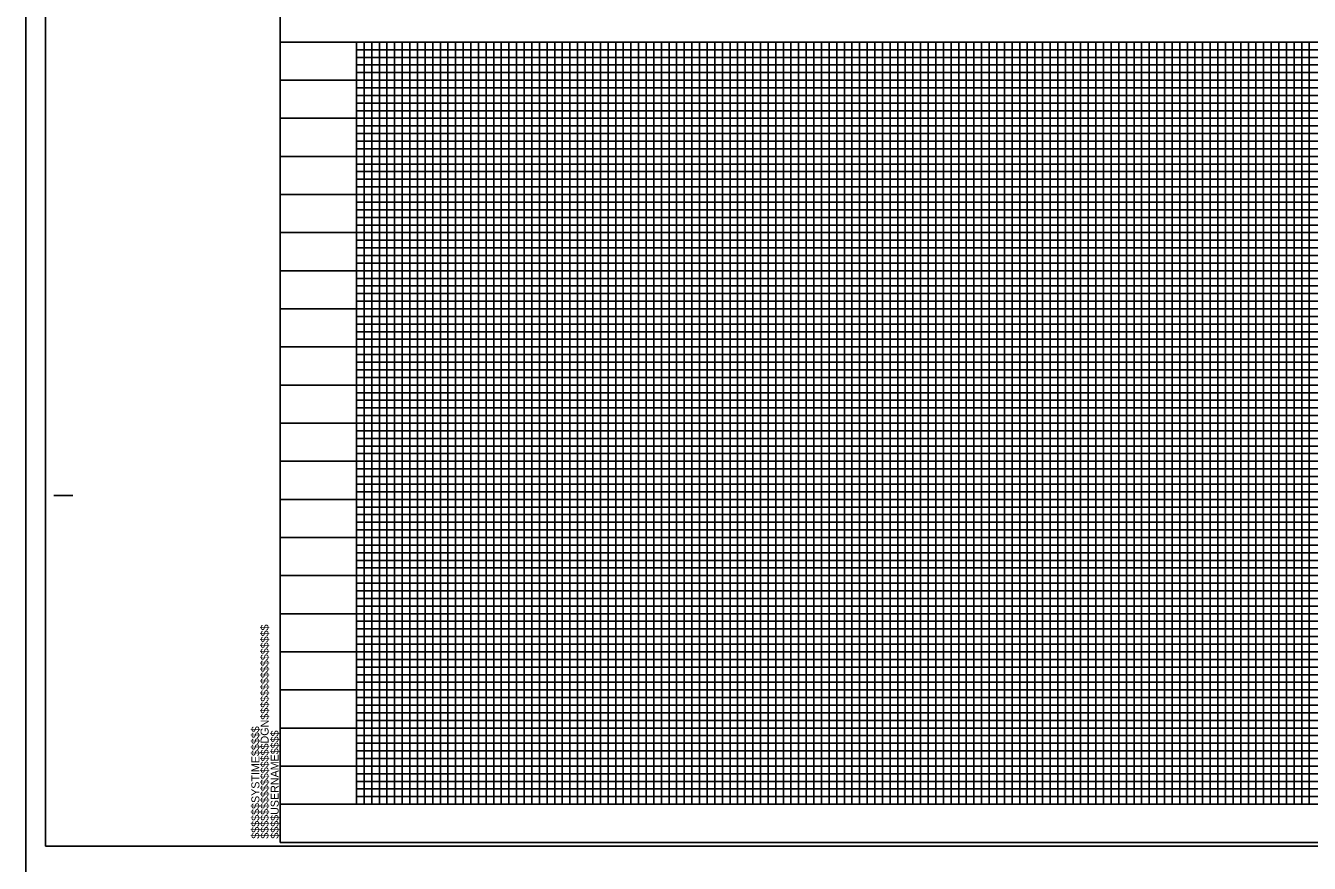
# Model space of a CAD drawing. Extents: x 1755181 to 1757273, y 729911 to 735411.
# Drawn here: x 1755181 to 1756023, y 732122 to 732672 of the extents above; entities that cross this region are included whole.
import ezdxf

# ---------------------------------------------------------------- set-up
doc = ezdxf.new("R2010")
doc.units = 0
for name, color, linetype in [('Scratch_Level_3', 7, 'Continuous'), ('Sheet Cutting Line CELL', 7, 'Continuous'), ('Sheet DOT Grid CELL', 7, 'Continuous'), ('Sheet Plot Border Inside CELL', 7, 'Continuous'), ('Sheet Plot Border Outside CELL', 7, 'Continuous'), ('Sheet Profile CELL', 7, 'Continuous'), ('Sheet Profile Grid Major CELL', 7, 'Continuous'), ('Sheet Profile Grid Middle CELL', 7, 'Continuous'), ('Sheet Profile Grid Minor CELL', 7, 'Continuous')]:
    doc.layers.add(name, color=color, linetype=linetype)

msp = doc.modelspace()

# ---------------------------------------------------------------- linework, layer by layer
at = {"layer": 'Scratch_Level_3'}
for points in [[(1755347.67, 732660.78), (1755347.67, 733185.78), (1756647.65, 733185.78), (1756647.63, 732952.8), (1756847.67, 732952.8), (1756847.67, 732660.78)], [(1755347.67, 732135.78), (1755347.67, 732660.78), (1756847.67, 732660.78), (1756847.67, 732135.78)]]:
    msp.add_lwpolyline(points, close=True, dxfattribs=at)
at = {"layer": 'Sheet Cutting Line CELL'}
msp.add_line((1755180.67, 733210.78), (1755180.67, 732110.78), dxfattribs=at)
at = {"layer": 'Sheet DOT Grid CELL'}
for p, q in [((1755347.67, 732660.78), (1756847.56, 732660.78)), ((1755397.67, 732660.78), (1755397.67, 732160.78)), ((1755447.67, 732660.78), (1755447.67, 732160.78)), ((1755497.67, 732660.78), (1755497.67, 732160.78)), ((1755547.67, 732660.78), (1755547.67, 732160.78)), ((1755597.67, 732660.78), (1755597.67, 732160.78)), ((1755647.67, 732660.78), (1755647.67, 732160.78)), ((1755697.67, 732660.78), (1755697.67, 732160.78)), ((1755747.67, 732660.78), (1755747.67, 732160.78)), ((1755797.67, 732660.78), (1755797.67, 732160.78)), ((1755847.67, 732660.78), (1755847.67, 732160.78)), ((1755897.67, 732660.78), (1755897.67, 732160.78)), ((1755947.67, 732660.78), (1755947.67, 732160.78)), ((1755997.67, 732660.78), (1755997.67, 732160.78)), ((1755347.67, 732610.78), (1756847.56, 732610.78)), ((1755347.67, 732560.78), (1756847.56, 732560.78)), ((1755347.67, 732510.78), (1756847.56, 732510.78)), ((1755347.67, 732460.78), (1756847.56, 732460.78)), ((1755347.67, 732410.78), (1756847.56, 732410.78)), ((1755347.67, 732360.78), (1756847.56, 732360.78)), ((1755347.67, 732310.78), (1756847.56, 732310.78)), ((1755347.67, 732260.78), (1756847.56, 732260.78)), ((1755347.67, 732210.78), (1756847.56, 732210.78))]:
    msp.add_line(p, q, dxfattribs=at)
at = {"layer": 'Sheet Plot Border Inside CELL'}
msp.add_lwpolyline([(1755193.67, 732133.23), (1756860.17, 732133.23), (1756860.17, 733188.33), (1755193.67, 733188.33)], close=True, dxfattribs=at)
at = {"layer": 'Sheet Plot Border Outside CELL'}
msp.add_lwpolyline([(1755180.67, 732110.78), (1756864.67, 732110.78), (1756864.67, 733210.78), (1755180.67, 733210.78)], close=True, dxfattribs=at)
at = {"layer": 'Sheet Profile CELL'}
for p, q in [((1755347.67, 732660.78), (1756847.67, 732660.78)), ((1755199.17, 732363.28), (1755211.67, 732363.28)), ((1756847.67, 732160.78), (1755347.67, 732160.78)), ((1755347.67, 732135.78), (1756847.67, 732135.78)), ((1755347.67, 732135.78), (1755347.67, 732135.78))]:
    msp.add_line(p, q, dxfattribs=at)
msp.add_lwpolyline([(1756847.67, 733185.78), (1755347.67, 733185.78), (1755347.67, 732135.78), (1756847.67, 732135.78)], close=True, dxfattribs=at)
msp.add_lwpolyline([(1755385.17, 732135.78), (1755385.17, 732135.78)], dxfattribs=at)
at = {"layer": 'Sheet Profile Grid Major CELL'}
for p, q in [((1755847.67, 732660.78), (1755897.67, 732660.78)), ((1755947.67, 732660.78), (1755997.67, 732660.78)), ((1755347.67, 732160.78), (1755347.67, 732160.78))]:
    msp.add_line(p, q, dxfattribs=at)
for points in [[(1755397.67, 732660.78), (1755397.67, 732160.78), (1755447.67, 732160.78), (1755447.67, 732660.78), (1755497.67, 732660.78), (1755497.67, 732160.78), (1755547.67, 732160.78), (1755547.67, 732660.78), (1755597.67, 732660.78), (1755597.67, 732160.78), (1755647.67, 732160.78), (1755647.67, 732660.78), (1755697.67, 732660.78), (1755697.67, 732160.78), (1755747.67, 732160.78), (1755747.67, 732660.78), (1755797.67, 732660.78), (1755797.67, 732160.78), (1755847.67, 732160.78), (1755847.67, 732660.78), (1755897.67, 732660.78), (1755897.67, 732160.78), (1755947.67, 732160.78), (1755947.67, 732660.78), (1755997.67, 732660.78), (1755997.67, 732160.78), (1756047.67, 732160.78)], [(1756847.67, 732610.78), (1755347.67, 732610.78)], [(1756847.67, 732560.78), (1755347.67, 732560.78), (1755347.67, 732510.78), (1756847.67, 732510.78)], [(1756847.67, 732460.78), (1755347.67, 732460.78), (1755347.67, 732410.78), (1756847.67, 732410.78)], [(1756847.67, 732360.78), (1755347.67, 732360.78), (1755347.67, 732310.78), (1756847.67, 732310.78)], [(1756847.67, 732260.78), (1755347.67, 732260.78), (1755347.67, 732260.78), (1755347.67, 732210.78), (1756847.67, 732210.78)], [(1756847.67, 732160.78), (1755347.67, 732160.78)]]:
    msp.add_lwpolyline(points, dxfattribs=at)
at = {"layer": 'Sheet Profile Grid Middle CELL'}
for points in [[(1755372.67, 732660.78), (1755422.67, 732660.78), (1755422.67, 732160.78), (1755472.67, 732160.78), (1755472.67, 732660.78), (1755522.67, 732660.78), (1755522.67, 732160.78), (1755572.67, 732160.78), (1755572.67, 732660.78), (1755622.67, 732660.78), (1755622.67, 732160.78), (1755672.67, 732160.78), (1755672.67, 732660.78), (1755722.67, 732660.78), (1755722.67, 732160.78), (1755772.67, 732160.78), (1755772.67, 732660.78), (1755822.67, 732660.78), (1755822.67, 732160.78), (1755872.67, 732160.78), (1755872.67, 732660.78), (1755922.67, 732660.78), (1755922.67, 732160.78), (1755972.67, 732160.78), (1755972.67, 732160.78), (1755972.67, 732660.78), (1756022.67, 732660.78), (1756022.67, 732160.78), (1756072.67, 732160.78)], [(1755347.67, 732635.78), (1756847.67, 732635.78)], [(1756847.67, 732585.78), (1755347.67, 732585.78), (1755347.67, 732535.78), (1756847.67, 732535.78)], [(1756847.67, 732485.78), (1755347.67, 732485.78), (1755347.67, 732435.78), (1756847.67, 732435.78)], [(1756847.67, 732385.78), (1755347.67, 732385.78), (1755347.67, 732335.78), (1756847.67, 732335.78)], [(1756847.67, 732285.78), (1755347.67, 732285.78), (1755347.67, 732235.78), (1756847.67, 732235.78)], [(1756847.67, 732185.78), (1755347.67, 732185.78)]]:
    msp.add_lwpolyline(points, dxfattribs=at)
at = {"layer": 'Sheet Profile Grid Minor CELL'}
for p, q in [((1755397.67, 732655.78), (1756797.67, 732655.78)), ((1756797.67, 732650.78), (1755397.67, 732650.78)), ((1755397.67, 732645.78), (1756797.67, 732645.78)), ((1756797.67, 732640.78), (1755397.67, 732640.78)), ((1755397.67, 732630.78), (1756797.67, 732630.78)), ((1756797.67, 732625.78), (1755397.67, 732625.78)), ((1755397.67, 732620.78), (1756797.67, 732620.78)), ((1756797.67, 732615.78), (1755397.67, 732615.78)), ((1755397.67, 732605.78), (1756797.67, 732605.78)), ((1756797.67, 732600.78), (1755397.67, 732600.78)), ((1755397.67, 732595.78), (1756797.67, 732595.78)), ((1756797.67, 732590.78), (1755397.67, 732590.78)), ((1755397.67, 732580.78), (1756797.67, 732580.78)), ((1756797.67, 732575.78), (1755397.67, 732575.78)), ((1755397.67, 732570.78), (1756797.67, 732570.78)), ((1756797.67, 732565.78), (1755397.67, 732565.78)), ((1755397.67, 732555.78), (1756797.67, 732555.78)), ((1756797.67, 732550.78), (1755397.67, 732550.78)), ((1755397.67, 732545.78), (1756797.67, 732545.78)), ((1756797.67, 732540.78), (1755397.67, 732540.78)), ((1755397.67, 732530.78), (1756797.67, 732530.78)), ((1756797.67, 732525.78), (1755397.67, 732525.78)), ((1755397.67, 732520.78), (1756797.67, 732520.78)), ((1756797.67, 732515.78), (1755397.67, 732515.78)), ((1755397.67, 732505.78), (1756797.67, 732505.78)), ((1756797.67, 732500.78), (1755397.67, 732500.78)), ((1755397.67, 732495.78), (1756797.67, 732495.78)), ((1756797.67, 732490.78), (1755397.67, 732490.78)), ((1755397.67, 732480.78), (1756797.67, 732480.78)), ((1756797.67, 732475.78), (1755397.67, 732475.78)), ((1755397.67, 732470.78), (1756797.67, 732470.78)), ((1756797.67, 732465.78), (1755397.67, 732465.93)), ((1755397.67, 732455.78), (1756797.67, 732455.78)), ((1756797.67, 732450.78), (1755397.67, 732450.78)), ((1755397.67, 732445.78), (1756797.67, 732445.78)), ((1756797.67, 732440.78), (1755397.67, 732440.78)), ((1755397.67, 732430.78), (1756797.67, 732430.78)), ((1756797.67, 732425.78), (1755397.67, 732425.78)), ((1755397.67, 732420.78), (1756797.67, 732420.78)), ((1756797.67, 732415.78), (1755397.67, 732415.78)), ((1755397.67, 732405.78), (1756797.67, 732405.78)), ((1756797.67, 732400.78), (1755397.67, 732400.78)), ((1755397.67, 732395.78), (1756797.67, 732395.78)), ((1756797.67, 732390.78), (1755397.67, 732390.78)), ((1755397.67, 732380.78), (1756797.67, 732380.78)), ((1756797.67, 732375.78), (1755397.67, 732375.78)), ((1755397.67, 732370.78), (1756797.67, 732370.78)), ((1756797.67, 732365.78), (1755397.67, 732365.78)), ((1755397.67, 732355.78), (1756797.67, 732355.78)), ((1756797.67, 732350.78), (1755397.67, 732350.78)), ((1755397.67, 732345.78), (1756797.67, 732345.78)), ((1756797.67, 732340.78), (1755397.67, 732340.78)), ((1755397.67, 732330.78), (1756797.67, 732330.78)), ((1756797.67, 732325.78), (1755397.67, 732325.78)), ((1755397.67, 732320.78), (1756797.67, 732320.78)), ((1756797.67, 732315.78), (1755397.67, 732315.78)), ((1755397.67, 732305.78), (1756797.67, 732305.78)), ((1756797.67, 732300.78), (1755397.67, 732300.78)), ((1755397.67, 732295.78), (1756797.67, 732295.78)), ((1756797.67, 732290.78), (1755397.67, 732290.78)), ((1755397.67, 732280.78), (1756797.67, 732280.78)), ((1756797.67, 732275.78), (1755397.67, 732275.78)), ((1755397.67, 732270.78), (1756797.67, 732270.78)), ((1756797.67, 732265.78), (1755397.67, 732265.78)), ((1755397.67, 732255.78), (1756797.67, 732255.78)), ((1756797.67, 732250.78), (1755397.67, 732250.78)), ((1755397.67, 732245.78), (1756797.67, 732245.78)), ((1756797.67, 732240.78), (1755397.67, 732240.78)), ((1755397.67, 732230.78), (1756797.67, 732230.78)), ((1756797.67, 732225.78), (1755397.67, 732225.78)), ((1755397.67, 732220.78), (1756797.67, 732220.78)), ((1756797.67, 732215.78), (1755397.67, 732215.78)), ((1755397.67, 732205.78), (1756797.67, 732205.78)), ((1756797.67, 732200.78), (1755397.67, 732200.78)), ((1755397.67, 732195.78), (1756797.67, 732195.78)), ((1756797.67, 732190.78), (1755397.67, 732190.78)), ((1755397.67, 732180.78), (1756797.67, 732180.78)), ((1756797.67, 732175.78), (1755397.67, 732175.78)), ((1755397.67, 732170.78), (1756797.67, 732170.78)), ((1755397.67, 732165.78), (1756797.67, 732165.78))]:
    msp.add_line(p, q, dxfattribs=at)
for points in [[(1755397.67, 732660.78), (1755402.67, 732660.78), (1755402.67, 732160.78), (1755407.67, 732160.78), (1755407.67, 732660.78), (1755412.67, 732660.78), (1755412.67, 732160.78), (1755417.67, 732160.78), (1755417.67, 732660.78), (1755427.67, 732660.78), (1755427.67, 732160.78), (1755432.67, 732160.78), (1755432.67, 732660.78), (1755437.67, 732660.78), (1755437.67, 732160.78), (1755442.67, 732160.78), (1755452.67, 732160.78), (1755457.67, 732160.78), (1755457.67, 732660.78), (1755462.67, 732660.78), (1755462.67, 732160.78), (1755467.67, 732160.78), (1755467.67, 732660.78), (1755477.67, 732660.78), (1755477.67, 732160.78), (1755482.67, 732160.78), (1755482.67, 732660.78), (1755487.67, 732660.78), (1755487.67, 732160.78), (1755492.67, 732160.78), (1755492.67, 732660.78), (1755502.67, 732660.78), (1755502.67, 732160.78), (1755507.67, 732160.78), (1755507.67, 732660.78), (1755512.67, 732660.78), (1755512.67, 732160.78), (1755517.67, 732160.78), (1755517.67, 732660.78), (1755527.67, 732660.78), (1755527.67, 732160.78), (1755532.67, 732160.78), (1755532.67, 732660.78), (1755537.67, 732660.78), (1755537.67, 732160.78), (1755542.67, 732160.78), (1755542.67, 732660.78), (1755552.67, 732660.78), (1755552.67, 732160.78), (1755557.67, 732160.78), (1755557.67, 732660.78), (1755562.67, 732660.78), (1755562.67, 732160.78), (1755567.67, 732160.78), (1755567.67, 732660.78), (1755577.67, 732660.78), (1755577.67, 732160.78), (1755582.67, 732160.78), (1755582.67, 732660.78), (1755587.67, 732660.78), (1755587.67, 732160.78), (1755592.67, 732160.78), (1755592.67, 732660.78), (1755602.67, 732660.78), (1755602.67, 732160.78), (1755607.67, 732160.78), (1755607.67, 732660.78), (1755612.67, 732660.78), (1755612.67, 732160.78)], [(1755442.67, 732160.78), (1755442.67, 732660.78), (1755452.67, 732660.78), (1755452.67, 732160.78)], [(1755612.67, 732160.78), (1755617.67, 732160.78), (1755617.67, 732660.78), (1755627.67, 732660.78), (1755627.67, 732160.78), (1755632.67, 732160.78), (1755632.67, 732660.78), (1755637.67, 732660.78), (1755637.67, 732160.78), (1755642.67, 732160.78), (1755642.67, 732660.78), (1755652.67, 732660.78), (1755652.67, 732160.78), (1755657.67, 732160.78), (1755657.67, 732660.78), (1755662.67, 732660.78), (1755662.67, 732160.78), (1755667.67, 732160.78), (1755667.67, 732660.78), (1755677.67, 732660.78), (1755677.67, 732160.78), (1755682.67, 732160.78), (1755682.67, 732660.78), (1755687.67, 732660.78), (1755687.67, 732160.78), (1755692.67, 732160.78), (1755692.67, 732660.78), (1755702.67, 732660.78), (1755702.67, 732160.78), (1755707.67, 732160.78), (1755707.67, 732660.78), (1755712.67, 732660.78), (1755712.67, 732160.78), (1755717.67, 732160.78), (1755717.67, 732660.78), (1755727.67, 732660.78), (1755727.67, 732160.78), (1755732.67, 732160.78), (1755732.67, 732660.78), (1755737.67, 732660.78), (1755737.67, 732160.78), (1755742.67, 732160.78), (1755742.67, 732660.78), (1755752.67, 732660.78), (1755752.67, 732160.78), (1755757.67, 732160.78), (1755757.67, 732660.78), (1755762.67, 732660.78), (1755762.67, 732160.78), (1755767.67, 732160.78), (1755767.67, 732660.78), (1755777.67, 732660.78), (1755777.67, 732160.78), (1755782.67, 732160.78), (1755782.67, 732660.78), (1755787.67, 732660.78), (1755787.67, 732160.78), (1755792.67, 732160.78), (1755792.67, 732660.78), (1755802.67, 732660.78), (1755802.67, 732160.78), (1755807.67, 732160.78), (1755807.67, 732660.78), (1755812.67, 732660.78), (1755812.67, 732160.78), (1755817.67, 732160.78), (1755817.67, 732660.78), (1755827.67, 732660.78), (1755827.67, 732160.78), (1755832.67, 732160.78), (1755832.67, 732660.78), (1755837.67, 732660.78), (1755837.67, 732160.78), (1755842.67, 732160.78), (1755842.67, 732660.78), (1755852.67, 732660.78), (1755852.67, 732160.78), (1755857.67, 732160.78), (1755857.67, 732660.78), (1755862.67, 732660.78), (1755862.67, 732160.78), (1755867.67, 732160.78), (1755867.67, 732660.78), (1755877.67, 732660.78), (1755877.67, 732160.78), (1755882.67, 732160.78), (1755882.67, 732660.78), (1755887.67, 732660.78), (1755887.67, 732160.78), (1755892.67, 732160.78), (1755892.67, 732660.78), (1755902.67, 732660.78), (1755902.67, 732160.78), (1755907.67, 732160.78), (1755907.67, 732660.78), (1755912.67, 732660.78), (1755912.67, 732160.78), (1755917.67, 732160.78), (1755917.67, 732660.78), (1755927.67, 732660.78)], [(1755927.67, 732660.78), (1755927.67, 732160.78), (1755932.67, 732160.78), (1755932.67, 732660.78), (1755937.67, 732660.78), (1755937.67, 732160.78), (1755942.67, 732160.78), (1755942.67, 732660.78), (1755952.67, 732660.78), (1755952.67, 732160.78), (1755957.67, 732160.78), (1755957.67, 732660.78), (1755962.67, 732660.78), (1755962.67, 732160.78), (1755967.67, 732160.78), (1755967.67, 732660.78), (1755977.67, 732660.78), (1755977.67, 732160.78), (1755982.67, 732160.78), (1755982.67, 732660.78), (1755987.67, 732660.78), (1755987.67, 732160.78), (1755992.67, 732160.78), (1755992.67, 732660.78), (1756002.67, 732660.78), (1756002.67, 732160.78), (1756007.67, 732160.78), (1756007.67, 732660.78), (1756012.67, 732660.78), (1756012.67, 732160.78), (1756017.67, 732160.78), (1756017.67, 732660.78), (1756027.67, 732660.78)]]:
    msp.add_lwpolyline(points, dxfattribs=at)

# ---------------------------------------------------------------- texts
at = {"layer": 'Sheet Profile CELL'}
for s, p in [('$$$$$$$$$$$$$$$$DGN$$$$$$$$$$$$$$$$', (1755340.03, 732138.16)), ('$$$$$$SYSTIME$$$$$', (1755333.98, 732138.16)), ('$$$$USERNAME$$$$', (1755346.61, 732138.17))]:
    msp.add_text(s, height=5.25, rotation=90, dxfattribs=at).set_placement(p)

doc.saveas('drawing.dxf')
